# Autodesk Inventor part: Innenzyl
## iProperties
Created: 2005-01
Part Number: Innenzyl
Document SubType Name: Modeling
Designer: Administrator
Manufacturer: Standard
Standards Organization: Custom
Material: Nylon-6/6
Author: Administrator
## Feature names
1. Extrusion1
